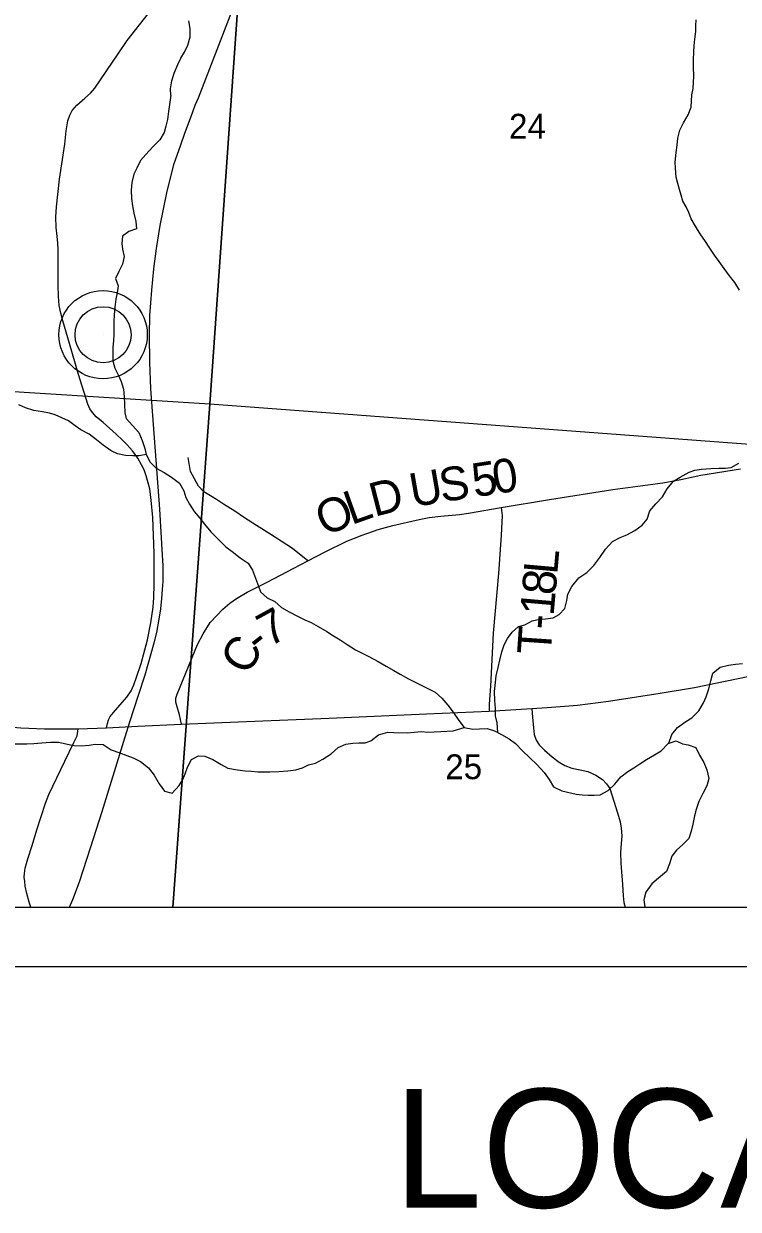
# Model space of a CAD drawing. Extents: x 0 to 34, y 0 to 22.
# Drawn here: x 3.804 to 5.007, y 13.591 to 15.589 of the extents above; entities that cross this region are included whole.
import ezdxf

# ---------------------------------------------------------------- set-up
doc = ezdxf.new("R2010")
doc.units = 0
for name, color, linetype in [('Default', 7, 'Continuous'), ('GM_X_County_Road', 7, 'Continuous'), ('GM_X_County_Road_Text', 7, 'Continuous'), ('GM_X_Minor_River', 7, 'Continuous'), ('GM_X_Rail_Line', 7, 'Continuous'), ('GM_X_Section', 7, 'Continuous'), ('GM_X_Section_Text', 7, 'Continuous'), ('GM_X_State_Route', 7, 'Continuous'), ('GM_X_Township_Road', 7, 'Continuous'), ('GM_X_Township_Road_Text', 7, 'Continuous'), ('GM_X_Unincorporated', 7, 'Continuous'), ('GM_X_Unincorporated_Location', 7, 'Continuous'), ('GM_X_US_Route', 7, 'Continuous'), ('SC_Scratch1', 7, 'Continuous'), ('SH_Data', 7, 'Continuous'), ('SH_Text', 7, 'Continuous')]:
    doc.layers.add(name, color=color, linetype=linetype)

msp = doc.modelspace()

# ---------------------------------------------------------------- linework, layer by layer
at = {"layer": 'Default'}
for points in [[(3.0447, 14.1), (4.0548, 14.1), (4.1172, 14.9476), (3.1079, 15.0113)], [(4.0548, 14.1), (5.0601, 14.1), (5.117, 14.8733), (4.1172, 14.9476)]]:
    msp.add_lwpolyline(points, close=True, dxfattribs=at)
at = {"layer": 'GM_X_County_Road'}
for points in [[(4.0696, 14.4085), (4.0661, 14.4244), (4.062, 14.4379), (4.06, 14.4456), (4.0598, 14.4525), (4.0619, 14.4592), (4.0963, 14.5428), (4.1057, 14.5605), (4.1177, 14.5797), (4.1288, 14.5917), (4.1388, 14.6023), (4.1506, 14.6125), (4.162, 14.6203), (4.18, 14.6307), (4.2126, 14.6474), (4.2822, 14.6836), (4.3112, 14.699), (4.3481, 14.7168), (4.3738, 14.7272), (4.4009, 14.7366), (4.4252, 14.7431), (4.4699, 14.7537), (4.4866, 14.7566), (4.506, 14.7588), (4.5374, 14.7621), (4.5529, 14.7641), (4.6078, 14.7738), (4.6892, 14.787), (4.7957, 14.8041), (4.8798, 14.8155), (4.9106, 14.8206), (4.9443, 14.8282), (5.0106, 14.8388)], [(3.8155, 14.1), (3.8132, 14.1085), (3.8091, 14.1233), (3.8064, 14.1354), (3.8055, 14.1434), (3.8047, 14.1504), (3.8049, 14.157), (3.8062, 14.1656), (3.8084, 14.1736), (3.8104, 14.1813), (3.8179, 14.2042), (3.8261, 14.2304), (3.8404, 14.2752), (3.8461, 14.2899), (3.8728, 14.3461), (3.8882, 14.3777), (3.8935, 14.3891), (3.8957, 14.4004)]]:
    msp.add_lwpolyline(points, dxfattribs=at)
at = {"layer": 'GM_X_Minor_River'}
for points in [[(4.0515, 15.4684), (4.0507, 15.4794), (4.0533, 15.4927), (4.0571, 15.5056), (4.0631, 15.5204), (4.0683, 15.5307), (4.0747, 15.5413), (4.08, 15.5527), (4.0841, 15.5667), (4.0841, 15.5811), (4.0818, 15.5936)], [(4.929, 15.469), (4.9312, 15.4797), (4.9315, 15.4903), (4.9323, 15.4998), (4.9318, 15.5161), (4.9318, 15.5278), (4.9325, 15.5423), (4.9329, 15.5517), (4.934, 15.5631), (4.9354, 15.576), (4.9358, 15.5855), (4.9361, 15.5957)], [(4.0515, 15.4684), (4.0494, 15.4528), (4.0475, 15.4411), (4.0459, 15.4278), (4.0429, 15.4161), (4.0402, 15.4054), (4.033, 15.3933), (4.0213, 15.3816), (4.0095, 15.3684), (4.0004, 15.3585), (3.9943, 15.3456), (3.9894, 15.3354), (3.9856, 15.3214), (3.9845, 15.3085), (3.9852, 15.2945), (3.9867, 15.282), (3.9893, 15.2695), (3.9923, 15.2554), (3.9934, 15.2433), (3.9809, 15.2388), (3.9703, 15.2312), (3.9692, 15.2187), (3.9699, 15.2089), (3.9729, 15.1967), (3.9703, 15.1835), (3.9642, 15.1714), (3.9585, 15.1596), (3.9626, 15.1471), (3.9611, 15.1357), (3.9588, 15.1248), (3.9573, 15.1111), (3.9561, 15.0982), (3.9553, 15.0869), (3.9553, 15.0656), (3.9549, 15.0543), (3.9538, 15.0437), (3.9537, 15.0209), (3.9571, 15.0084), (3.9631, 14.9959), (3.968, 14.986), (3.9718, 14.9731), (3.9729, 14.9603), (3.9733, 14.9478), (3.974, 14.9334), (3.9763, 14.9235), (3.9868, 14.9117), (3.9978, 14.9), (4.0034, 14.8867), (4.0079, 14.873), (4.0102, 14.8632), (4.0166, 14.8499), (4.0268, 14.8397), (4.04, 14.8325), (4.0525, 14.8249), (4.0661, 14.8146), (4.0736, 14.8017), (4.077, 14.7907), (4.0827, 14.7793), (4.0906, 14.7672), (4.1004, 14.7558), (4.1083, 14.7456), (4.1189, 14.7327), (4.1442, 14.7072), (4.1548, 14.6993), (4.1684, 14.6886), (4.1816, 14.6799), (4.1891, 14.6678), (4.194, 14.6545), (4.1993, 14.6412), (4.2023, 14.6317), (4.2136, 14.6215), (4.2265, 14.6154), (4.2378, 14.6052), (4.2507, 14.5976), (4.265, 14.5903), (4.2771, 14.5846), (4.2877, 14.5797), (4.2998, 14.5732), (4.3142, 14.5645), (4.3255, 14.5573), (4.3364, 14.5508), (4.3485, 14.5425), (4.3625, 14.5337), (4.3739, 14.528), (4.3848, 14.5223), (4.4007, 14.5143), (4.4139, 14.5064), (4.4271, 14.4988), (4.4377, 14.4927), (4.4517, 14.4851), (4.4729, 14.4744), (4.4853, 14.468), (4.4967, 14.4627), (4.508, 14.4524), (4.5178, 14.4403), (4.5269, 14.4285), (4.5367, 14.4148), (4.5457, 14.4027), (4.5601, 14.4), (4.5714, 14.4008), (4.5843, 14.4011)], [(4.9279, 15.4481), (4.929, 15.469)], [(5.0091, 15.1402), (5.0012, 15.1531), (4.9925, 15.1641), (4.9834, 15.1767), (4.9748, 15.188), (4.9672, 15.199), (4.9582, 15.2127), (4.9521, 15.2222), (4.9431, 15.2351), (4.9348, 15.2476), (4.928, 15.2601), (4.9238, 15.2707), (4.9193, 15.2802), (4.914, 15.2901), (4.9107, 15.3003), (4.908, 15.3098), (4.9054, 15.3196), (4.9024, 15.3303), (4.9013, 15.3454), (4.9009, 15.3557), (4.9025, 15.3719), (4.9044, 15.3841), (4.9055, 15.3962), (4.9089, 15.4098), (4.9146, 15.422), (4.9226, 15.4352), (4.9279, 15.4481)], [(4.0102, 14.8632), (3.9981, 14.8609), (3.9875, 14.8609), (3.975, 14.8613), (3.9618, 14.864), (3.9508, 14.8693), (3.9376, 14.8785), (3.9263, 14.8876), (3.9138, 14.8974), (3.9002, 14.9043), (3.8904, 14.9115), (3.879, 14.9199), (3.8677, 14.9248), (3.8568, 14.9297), (3.8469, 14.9328), (3.8352, 14.9351), (3.8205, 14.9374), (3.8065, 14.9419), (3.7955, 14.9469)], [(4.6022, 14.3943), (4.601, 14.4106), (4.598, 14.4227), (4.598, 14.4348), (4.5969, 14.4485), (4.5965, 14.4633), (4.5977, 14.4735), (4.5996, 14.4902), (4.603, 14.5038), (4.6057, 14.5163), (4.6091, 14.5303), (4.6129, 14.5421), (4.6182, 14.5527), (4.6266, 14.5633), (4.6368, 14.5731), (4.6474, 14.5757), (4.6602, 14.5829), (4.6724, 14.5856), (4.6822, 14.5863), (4.6954, 14.5878), (4.7053, 14.5931), (4.7151, 14.6037), (4.7185, 14.6169), (4.7201, 14.6276), (4.7269, 14.6408), (4.7387, 14.6552), (4.7523, 14.6639), (4.7636, 14.676), (4.7739, 14.6892), (4.7834, 14.7036), (4.7951, 14.7161), (4.8084, 14.7229), (4.8197, 14.7278), (4.833, 14.735), (4.8454, 14.7441), (4.8538, 14.7539), (4.8583, 14.7683), (4.8682, 14.7797), (4.8796, 14.7914), (4.8875, 14.8054), (4.8981, 14.8183), (4.9095, 14.8247), (4.9243, 14.833), (4.9341, 14.8368), (4.9451, 14.8383), (4.961, 14.8394), (4.975, 14.8398), (4.9848, 14.8398), (4.995, 14.8413), (5.0082, 14.8484)], [(4.8901, 14.3763), (4.8952, 14.3912), (4.9046, 14.4029), (4.9187, 14.4128), (4.9289, 14.4192), (4.9406, 14.4309), (4.9486, 14.4445), (4.9531, 14.4548), (4.9577, 14.468), (4.9611, 14.4813), (4.9642, 14.4945), (4.9767, 14.5048), (4.9907, 14.5078), (5.0024, 14.5096), (5.0145, 14.5108)], [(4.3884, 14.3802), (4.4012, 14.3904), (4.4171, 14.3949), (4.4273, 14.3942), (4.4493, 14.3941), (4.4614, 14.3949), (4.4739, 14.396), (4.4841, 14.3952), (4.495, 14.3956), (4.506, 14.3963), (4.5272, 14.3971), (4.5457, 14.4027)], [(4.5843, 14.4011), (4.5964, 14.3973), (4.6085, 14.3909), (4.621, 14.384), (4.6319, 14.3757), (4.6436, 14.3635), (4.6553, 14.3525), (4.6682, 14.34), (4.6802, 14.3271), (4.6889, 14.3153), (4.6961, 14.3028), (4.7101, 14.296), (4.7339, 14.2906), (4.7441, 14.2895), (4.7543, 14.2891), (4.7645, 14.2891), (4.7747, 14.2894), (4.788, 14.2966), (4.799, 14.3076), (4.8096, 14.3197), (4.8213, 14.3288), (4.8315, 14.3348), (4.8414, 14.3416), (4.8524, 14.3488), (4.866, 14.3571), (4.877, 14.3636), (4.8891, 14.376), (4.9023, 14.3802), (4.9129, 14.3752), (4.9228, 14.3737), (4.9356, 14.3692), (4.942, 14.3563), (4.9492, 14.3437), (4.9541, 14.3316), (4.9575, 14.3168), (4.9544, 14.3043), (4.9472, 14.2918), (4.9407, 14.2782), (4.9362, 14.2649), (4.9335, 14.2539), (4.9305, 14.2399), (4.9278, 14.2282), (4.924, 14.2157), (4.9138, 14.2055), (4.9028, 14.1964), (4.8952, 14.1862), (4.8914, 14.1733), (4.8861, 14.1604), (4.8725, 14.1491), (4.8615, 14.1392), (4.8516, 14.1256), (4.8482, 14.1127), (4.8497, 14.1006), (4.85, 14.1)], [(3.7726, 14.3754), (3.8089, 14.3754), (3.821, 14.3761), (3.8343, 14.3772), (3.849, 14.378), (3.8627, 14.378), (3.8748, 14.3753), (3.8884, 14.3726), (3.9008, 14.3718), (3.9137, 14.3733), (3.9239, 14.3748), (3.9375, 14.3741), (3.9511, 14.3653), (3.9655, 14.36), (3.9772, 14.3558), (3.9878, 14.3516), (4.0006, 14.3455), (4.0139, 14.3349), (4.0233, 14.3224), (4.0316, 14.308), (4.041, 14.2958), (4.0535, 14.2924), (4.0653, 14.3049), (4.0717, 14.3151), (4.0759, 14.325), (4.0797, 14.3359), (4.0861, 14.3488), (4.0979, 14.3552), (4.1088, 14.3545), (4.1224, 14.3488), (4.1364, 14.3404), (4.1477, 14.3343), (4.1636, 14.3313), (4.1769, 14.3301), (4.1875, 14.3293), (4.198, 14.3282), (4.2181, 14.3282), (4.2336, 14.3289), (4.2487, 14.33), (4.262, 14.3315), (4.2733, 14.3349), (4.2832, 14.3398), (4.2953, 14.3428), (4.3074, 14.3496), (4.3214, 14.3583), (4.3331, 14.3693), (4.346, 14.3746), (4.3581, 14.3765), (4.3679, 14.3768), (4.3785, 14.3768), (4.3884, 14.3802)]]:
    msp.add_lwpolyline(points, dxfattribs=at)
at = {"layer": 'GM_X_Rail_Line'}
msp.add_lwpolyline([(3.8809, 14.1), (3.8865, 14.1132), (3.8976, 14.1428), (3.9167, 14.2016), (3.9357, 14.2614), (3.9724, 14.3797), (3.9824, 14.4123), (3.9965, 14.4556), (4.0082, 14.4917), (4.0237, 14.5454), (4.028, 14.5628), (4.0321, 14.5854), (4.0346, 14.6029), (4.0366, 14.6203), (4.0377, 14.6356), (4.0384, 14.649), (4.0385, 14.6759), (4.0376, 14.6936), (4.0327, 14.7706), (4.018, 14.9735), (4.0159, 15.0188), (4.0155, 15.064), (4.0164, 15.097), (4.0193, 15.1397), (4.0227, 15.176), (4.0272, 15.2102), (4.0337, 15.2489), (4.045, 15.3039), (4.0567, 15.3517), (4.0684, 15.385), (4.0749, 15.4048), (4.083, 15.4254), (4.0883, 15.4403), (4.0925, 15.4518), (4.098, 15.4643), (4.1545, 15.6095)], dxfattribs=at)
at = {"layer": 'GM_X_Section'}
for points in [[(4.189, 15.9719), (4.1172, 14.9476), (3.1079, 15.0113), (3.1721, 16.0496)], [(5.1915, 15.9177), (5.117, 14.8733), (4.1172, 14.9476), (4.189, 15.9719)]]:
    msp.add_lwpolyline(points, close=True, dxfattribs=at)
at = {"layer": 'GM_X_State_Route'}
msp.add_lwpolyline([(3.943, 14.4026), (3.9447, 14.4097), (3.9463, 14.4156), (3.9494, 14.4213), (3.9547, 14.428), (3.9696, 14.4449), (3.9775, 14.4539), (3.9845, 14.4647), (3.9891, 14.4749), (3.993, 14.4861), (4.0014, 14.511), (4.0121, 14.5509), (4.0179, 14.5791), (4.0217, 14.6056), (4.0228, 14.6222), (4.0236, 14.6437), (4.0236, 14.6966), (4.0213, 14.7568), (4.0185, 14.7858), (4.016, 14.8051), (4.0135, 14.8154), (4.0099, 14.8272), (4.0064, 14.8369), (4.0023, 14.8455), (3.9959, 14.8569), (3.9871, 14.869), (3.978, 14.8793), (3.9699, 14.8874), (3.9592, 14.8975), (3.9373, 14.9171), (3.9259, 14.9265), (3.9196, 14.9335), (3.915, 14.9399), (3.9116, 14.9477), (3.8961, 14.9979), (3.881, 15.05), (3.8696, 15.0884), (3.866, 15.1013), (3.8635, 15.1143), (3.8623, 15.1296), (3.8617, 15.1476), (3.8616, 15.2085), (3.861, 15.2193), (3.8598, 15.2309), (3.8584, 15.2453), (3.8577, 15.2637), (3.8587, 15.2804), (3.8642, 15.3273), (3.8728, 15.3862), (3.8753, 15.4083), (3.8781, 15.4256), (3.8812, 15.4349), (3.8853, 15.4427), (3.8931, 15.4519), (3.9068, 15.4635), (3.9161, 15.4717), (3.9237, 15.4806), (3.9629, 15.5381), (3.9777, 15.5609), (4.0133, 15.6056)], dxfattribs=at)
at = {"layer": 'GM_X_Township_Road'}
for points in [[(4.2822, 14.6836), (4.2563, 14.7046), (4.2197, 14.7281), (4.1958, 14.7436), (4.1753, 14.756), (4.1591, 14.7674), (4.14, 14.7791), (4.1282, 14.787), (4.1182, 14.7935), (4.1069, 14.8003), (4.0979, 14.8098), (4.0846, 14.8345), (4.0805, 14.858)], [(4.6078, 14.7738), (4.6095, 14.7603), (4.6078, 14.7268), (4.6031, 14.6625), (4.5941, 14.5617), (4.5899, 14.4728), (4.5874, 14.442), (4.5874, 14.4303)], [(4.6596, 14.4348), (4.6608, 14.4201), (4.6622, 14.4024), (4.6635, 14.391), (4.6668, 14.3817), (4.6719, 14.3739), (4.6808, 14.3645), (4.6935, 14.3537), (4.7057, 14.3447), (4.7149, 14.3388), (4.7268, 14.3344), (4.7408, 14.3314), (4.7537, 14.3286), (4.7671, 14.3224), (4.7783, 14.3153), (4.785, 14.3079), (4.7907, 14.3001), (4.7976, 14.2787), (4.8036, 14.259), (4.8082, 14.2438), (4.81, 14.2332), (4.811, 14.2203), (4.81, 14.2075), (4.8087, 14.1923), (4.8091, 14.1744), (4.8119, 14.1385), (4.8133, 14.1192), (4.8146, 14.1081), (4.8169, 14.1)]]:
    msp.add_lwpolyline(points, dxfattribs=at)
at = {"layer": 'GM_X_Unincorporated'}
for radius in [0.0744, 0.0472]:
    msp.add_circle((3.9374, 15.0649), radius, dxfattribs=at)
at = {"layer": 'GM_X_Unincorporated_Location'}
msp.add_line((3.9374, 15.0649), (3.9374, 15.0649), dxfattribs=at)
at = {"layer": 'GM_X_US_Route'}
for points in [[(3.9957, 14.405), (4.0696, 14.4085), (4.1647, 14.4122), (4.3183, 14.4189), (4.4823, 14.426), (4.5874, 14.4303), (4.6235, 14.4326), (4.6596, 14.4348), (4.6854, 14.4367), (4.7362, 14.4408), (4.7884, 14.447), (4.8756, 14.4606), (4.9333, 14.4703), (5.0807, 14.5008), (5.0816, 14.501), (5.222, 14.53), (5.4268, 14.5725)], [(3.619, 14.4296), (3.6567, 14.4216), (3.6946, 14.4147), (3.7323, 14.4092), (3.7712, 14.4046), (3.7989, 14.4026), (3.839, 14.4009), (3.8649, 14.4004), (3.8957, 14.4004), (3.943, 14.4026), (3.9957, 14.405)]]:
    msp.add_lwpolyline(points, dxfattribs=at)
at = {"layer": 'SC_Scratch1'}
msp.add_lwpolyline([(2.1, 19.1982), (2.1, 14.1), (5.0535, 14.1), (5.0814, 14.5016), (5.1049, 14.8414), (5.1794, 15.9156), (5.2761, 17.2534), (5.2869, 17.4026), (5.3506, 18.2846), (5.3662, 18.4999), (5.4007, 18.9779), (5.182, 18.9932), (4.7997, 19.0196), (4.7394, 19.0241), (4.3628, 19.0495), (3.3448, 19.1146), (2.3572, 19.1804)], close=True, dxfattribs=at)
at = {"layer": 'SH_Data'}
for p, q in [((2.1, 14.1), (8.9, 14.1)), ((2, 14), (9, 14))]:
    msp.add_line(p, q, dxfattribs=at)

# ---------------------------------------------------------------- texts
at = {"layer": 'GM_X_County_Road_Text'}
for s, rotation, p in [('5', 8.6292, (4.5628, 14.7908)), ('0', 8.6292, (4.5974, 14.7961)), ('U', 9.9067, (4.4587, 14.7739)), ('S', 8.6616, (4.5076, 14.7824)), ('D', 14.4842, (4.3944, 14.7577)), ('O', 23.4014, (4.3107, 14.7244)), ('L', 19.5774, (4.3556, 14.7439)), ('7', 28.581, (4.2169, 14.5378)), ('C', 59.1494, (4.1805, 14.4887)), ('-', 38.5672, (4.2009, 14.5247))]:
    msp.add_text(s, height=0.0568, rotation=rotation, dxfattribs=at).set_placement(p)
at = {"layer": 'GM_X_Section_Text'}
for s, p in [('24', (4.621, 15.3953)), ('25', (4.5135, 14.3158))]:
    msp.add_text(s, height=0.04186, rotation=0, dxfattribs=at).set_placement(p)
at = {"layer": 'GM_X_Township_Road_Text'}
for s, rotation, p in [('L', 84.8932, (4.7021, 14.6596)), ('8', 84.9196, (4.699, 14.6247)), ('1', 85.0242, (4.696, 14.5899)), ('-', 85.2169, (4.6941, 14.5667)), ('T', 86.0713, (4.6912, 14.5245))]:
    msp.add_text(s, height=0.0568, rotation=rotation, dxfattribs=at).set_placement(p)
at = {"layer": 'SH_Text'}
msp.add_text('LOCATION MAP', height=0.2, dxfattribs=at).set_placement((4.4269, 13.5938))

doc.saveas('drawing.dxf')
